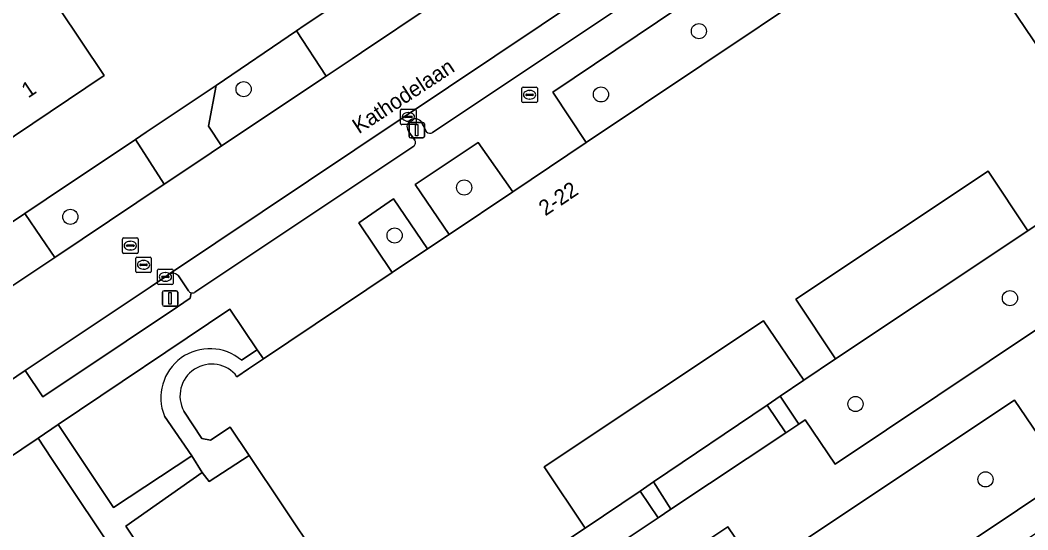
# Model space of a CAD drawing. Extents: x 158793 to 159888, y 384317 to 385256.
# Drawn here: x 158844.5 to 158909.7, y 384549.7 to 384582.6 of the extents above; entities that cross this region are included whole.
import ezdxf

# ---------------------------------------------------------------- set-up
doc = ezdxf.new("R2010")
doc.units = 0
for name, color, linetype in [('IMGEO_Berm_groen', 7, 'Continuous'), ('IMGEO_Boom', 7, 'Continuous'), ('IMGEO_Brandkraan', 7, 'Continuous'), ('IMGEO_Erf', 7, 'Continuous'), ('IMGEO_Groenvoorziening', 7, 'Continuous'), ('IMGEO_Inrit_open', 7, 'Continuous'), ('IMGEO_Kolk', 7, 'Continuous'), ('IMGEO_Lichtmast', 7, 'Continuous'), ('IMGEO_Openbare_ruimte_label', 7, 'Continuous'), ('IMGEO_Pand', 7, 'Continuous'), ('IMGEO_Pand_nummerreeks', 7, 'Continuous'), ('IMGEO_Pand_overbouw', 7, 'Continuous'), ('IMGEO_Parkeervlak_open', 7, 'Continuous'), ('IMGEO_Rijbaan_lokaal_open', 7, 'Continuous'), ('IMGEO_Rioolput', 7, 'Continuous'), ('IMGEO_Voetpad_gesloten', 7, 'Continuous'), ('IMGEO_Voetpad_halfverhard', 7, 'Continuous'), ('IMGEO_Voetpad_open', 7, 'Continuous')]:
    doc.layers.add(name, color=color, linetype=linetype)

msp = doc.modelspace()

# ---------------------------------------------------------------- linework, layer by layer
at = {"layer": 'IMGEO_Berm_groen'}
for points in [[(158854.32, 384566.248), (158854.199, 384566.219), (158854.173, 384566.208), (158854.147, 384566.195), (158854.099, 384566.166), (158853.914, 384566.031), (158852.903, 384565.347), (158844.83, 384559.95), (158845.97, 384558.247), (158851.361, 384561.842)], [(158855.384, 384565.105), (158854.738, 384566.065)], [(158851.361, 384561.842), (158854.669, 384564.066), (158855.499, 384564.624), (158855.562, 384564.977)]]:
    msp.add_lwpolyline(points, dxfattribs=at)
for centre, radius, start, end in [((158854.364, 384565.78), 0.47, 37.32016, 95.39233), ((158855.636, 384565.267), 0.299, 212.78458, 255.77551)]:
    msp.add_arc(centre, radius, start, end, dxfattribs=at)
at = {"layer": 'IMGEO_Boom'}
for centre in [(158888.4, 384581.893), (158858.951, 384578.145), (158882.064, 384577.805), (158873.216, 384571.784), (158847.744, 384569.893), (158868.717, 384568.685), (158908.517, 384564.632), (158898.529, 384557.786), (158906.935, 384552.912)]:
    msp.add_circle(centre, 0.489, dxfattribs=at)
at = {"layer": 'IMGEO_Brandkraan'}
for p, q in [((158876.948, 384577.354), (158876.948, 384578.206)), ((158877.023, 384578.28), (158877.875, 384578.28)), ((158877.949, 384578.206), (158877.949, 384577.354)), ((158877.207, 384577.774), (158877.207, 384577.786)), ((158877.645, 384577.737), (158877.247, 384577.737)), ((158877.25, 384577.823), (158877.648, 384577.823)), ((158877.436, 384578.06), (158877.461, 384578.06)), ((158877.691, 384577.786), (158877.691, 384577.774)), ((158877.875, 384577.28), (158877.023, 384577.28)), ((158877.459, 384577.5), (158877.434, 384577.5))]:
    msp.add_line(p, q, dxfattribs=at)
for points in [[(158876.948, 384577.354), (158876.948, 384578.206)], [(158877.023, 384578.28), (158877.875, 384578.28)], [(158877.949, 384578.206), (158877.949, 384577.354)], [(158877.875, 384577.28), (158877.023, 384577.28)]]:
    msp.add_lwpolyline(points, dxfattribs=at)
for centre, radius, start, end in [((158877.025, 384578.204), 0.0765, 91.55205, 178.44795), ((158877.025, 384578.204), 0.0765, 91.55205, 178.44795), ((158877.873, 384578.204), 0.0765, 1.55205, 88.44795), ((158877.873, 384578.204), 0.0765, 1.55205, 88.44795), ((158877.247, 384577.783), 0.0403, 85.87752, 175.75265), ((158877.244, 384577.773), 0.0366, 178.93798, 274.71019), ((158877.648, 384577.78), 0.043, 264.86636, 352.45326), ((158877.652, 384577.785), 0.0386, 1.73085, 96.63898), ((158877.025, 384577.356), 0.0765, 181.55205, 268.44795), ((158877.025, 384577.356), 0.0765, 181.55205, 268.44795), ((158877.873, 384577.356), 0.0765, 271.55205, 358.44795), ((158877.873, 384577.356), 0.0765, 271.55205, 358.44795)]:
    msp.add_arc(centre, radius, start, end, dxfattribs=at)
for centre, major_axis, ratio, start_param, end_param in [((158877.435, 384577.78), (-0.387, 0.002), 0.722429, 4.712389, 7.853982), ((158877.46, 384577.78), (-0.39, 0.002), 0.717154, 1.570796, 4.712389)]:
    msp.add_ellipse(centre, major_axis=major_axis, ratio=ratio, start_param=start_param, end_param=end_param, dxfattribs=at)
at = {"layer": 'IMGEO_Erf'}
msp.add_lwpolyline([(158815.511, 384607.239), (158824.8, 384593.502), (158838.699, 384572.93), (158841.845, 384568.15), (158844.791, 384570.111), (158846.183, 384571.037), (158851.961, 384574.901), (158852.64, 384575.355), (158857.172, 384578.386), (158862.362, 384581.922), (158862.863, 384582.253), (158870.987, 384587.696), (158871.33, 384587.937), (158876.65, 384591.488), (158877.708, 384592.194), (158878.556, 384592.76), (158881.626, 384594.81), (158903.507, 384608.931), (158902.593, 384610.317), (158898.058, 384617.173), (158883.161, 384639.419), (158896.259, 384659.409)], dxfattribs=at)
for points in [[(158849.483, 384585.076), (158846.99, 384583.407), (158849.927, 384579.02), (158841.803, 384573.58), (158836.037, 384582.224), (158846.653, 384589.345)], [(158909.672, 384568.992), (158907.106, 384572.842), (158894.671, 384564.558), (158897.236, 384560.707)], [(158892.814, 384557.716), (158893.655, 384558.284), (158895.186, 384559.32), (158892.571, 384563.159), (158878.397, 384553.717), (158881.04, 384549.751), (158884.602, 384552.16), (158885.469, 384552.747)]]:
    msp.add_lwpolyline(points, close=True, dxfattribs=at)
at = {"layer": 'IMGEO_Groenvoorziening'}
for points in [[(158896.066, 384584.721), (158893.869, 384587.99), (158878.954, 384577.951), (158881.101, 384574.689)], [(158864.28, 384578.99), (158862.362, 384581.922), (158857.172, 384578.386), (158856.672, 384575.759), (158857.528, 384574.48)], [(158853.808, 384571.995), (158851.961, 384574.901), (158846.183, 384571.037), (158844.791, 384570.111), (158845.852, 384568.549), (158846.731, 384567.269)], [(158874.127, 384574.707), (158870.056, 384571.973), (158872.253, 384568.757), (158876.359, 384571.51)], [(158920.463, 384569.434), (158917.313, 384574.089), (158915.672, 384572.989), (158909.672, 384568.992), (158897.236, 384560.707), (158895.186, 384559.32), (158893.655, 384558.284), (158894.867, 384556.489), (158895.279, 384556.763), (158897.216, 384553.897)], [(158868.652, 384571.046), (158866.399, 384569.501), (158868.57, 384566.288), (158870.855, 384567.82)], [(158912.188, 384553.057), (158908.819, 384558.044), (158892.215, 384546.967), (158890.278, 384549.853), (158884.582, 384546.051), (158889.87, 384538.118)], [(158894.012, 384555.92), (158892.814, 384557.716), (158885.469, 384552.747), (158886.593, 384550.985)], [(158846.53, 384554.269), (158845.658, 384555.582), (158838.061, 384550.476), (158839.557, 384548.32), (158837.723, 384547.037), (158838.14, 384546.442), (158839.403, 384544.582), (158841.647, 384546.027), (158842.852, 384544.03), (158840.786, 384542.544), (158851.128, 384527.309), (158860.392, 384533.498)], [(158859.32, 384554.45), (158856.721, 384552.773), (158856.279, 384553.362), (158851.333, 384549.895), (158861.674, 384534.354), (158872.769, 384541.766), (158871.634, 384543.486), (158868.183, 384541.187)], [(158885.76, 384550.431), (158884.602, 384552.16), (158881.04, 384549.751), (158872.46, 384544.036), (158873.576, 384542.305), (158881.227, 384547.416)]]:
    msp.add_lwpolyline(points, close=True, dxfattribs=at)
msp.add_lwpolyline([(158858.814, 384560.615), (158859.837, 384561.3), (158858.056, 384563.917), (158846.964, 384556.461), (158850.531, 384551.1), (158855.606, 384554.43), (158853.829, 384557.007)], dxfattribs=at)
msp.add_arc((158856.767, 384558.196), 3.169, 49.75731, 202.03457, dxfattribs=at)
at = {"layer": 'IMGEO_Inrit_open'}
msp.add_lwpolyline([(158871.218, 384583.628), (158873.243, 384584.982), (158871.33, 384587.937), (158870.987, 384587.696), (158862.863, 384582.253), (158862.362, 384581.922), (158864.28, 384578.99), (158865.964, 384580.114), (158866.578, 384580.525)], close=True, dxfattribs=at)
at = {"layer": 'IMGEO_Kolk'}
for p, q in [((158869.104, 384575.924), (158869.104, 384576.776)), ((158869.179, 384576.85), (158870.031, 384576.85)), ((158869.363, 384576.344), (158869.363, 384576.356)), ((158869.801, 384576.307), (158869.403, 384576.307)), ((158869.406, 384576.393), (158869.804, 384576.393)), ((158869.592, 384576.63), (158869.617, 384576.63)), ((158869.847, 384576.356), (158869.847, 384576.344)), ((158870.105, 384576.776), (158870.105, 384575.924)), ((158870.031, 384575.85), (158869.179, 384575.85)), ((158869.615, 384576.07), (158869.59, 384576.07)), ((158853.464, 384566.508), (158854.316, 384566.508)), ((158853.389, 384565.582), (158853.389, 384566.434)), ((158853.648, 384566.002), (158853.648, 384566.014)), ((158854.086, 384565.965), (158853.688, 384565.965)), ((158853.691, 384566.051), (158854.089, 384566.051)), ((158853.877, 384566.288), (158853.902, 384566.288)), ((158854.132, 384566.014), (158854.132, 384566.002)), ((158854.39, 384566.434), (158854.39, 384565.582)), ((158854.316, 384565.508), (158853.464, 384565.508)), ((158853.9, 384565.728), (158853.875, 384565.728))]:
    msp.add_line(p, q, dxfattribs=at)
for points in [[(158869.104, 384575.924), (158869.104, 384576.776)], [(158869.179, 384576.85), (158870.031, 384576.85)], [(158870.105, 384576.776), (158870.105, 384575.924)], [(158870.031, 384575.85), (158869.179, 384575.85)], [(158853.464, 384566.508), (158854.316, 384566.508)], [(158853.389, 384565.582), (158853.389, 384566.434)], [(158854.39, 384566.434), (158854.39, 384565.582)], [(158854.316, 384565.508), (158853.464, 384565.508)]]:
    msp.add_lwpolyline(points, dxfattribs=at)
for centre, radius, start, end in [((158869.181, 384576.774), 0.0765, 91.55205, 178.44795), ((158869.181, 384576.774), 0.0765, 91.55205, 178.44795), ((158869.403, 384576.353), 0.0403, 85.87752, 175.75265), ((158869.4, 384576.343), 0.0366, 178.93798, 274.71019), ((158869.804, 384576.35), 0.043, 264.86636, 352.45326), ((158869.808, 384576.355), 0.0386, 1.73085, 96.63898), ((158870.029, 384576.774), 0.0765, 1.55205, 88.44795), ((158870.029, 384576.774), 0.0765, 1.55205, 88.44795), ((158869.181, 384575.926), 0.0765, 181.55205, 268.44795), ((158869.181, 384575.926), 0.0765, 181.55205, 268.44795), ((158870.029, 384575.926), 0.0765, 271.55205, 358.44795), ((158870.029, 384575.926), 0.0765, 271.55205, 358.44795), ((158853.466, 384566.432), 0.0765, 91.55205, 178.44795), ((158853.466, 384566.432), 0.0765, 91.55205, 178.44795), ((158854.314, 384566.432), 0.0765, 1.55205, 88.44795), ((158854.314, 384566.432), 0.0765, 1.55205, 88.44795), ((158853.688, 384566.011), 0.0403, 85.87752, 175.75265), ((158853.685, 384566.001), 0.0366, 178.93798, 274.71019), ((158854.089, 384566.008), 0.043, 264.86636, 352.45326), ((158854.093, 384566.013), 0.0386, 1.73085, 96.63898), ((158853.466, 384565.584), 0.0765, 181.55205, 268.44795), ((158853.466, 384565.584), 0.0765, 181.55205, 268.44795), ((158854.314, 384565.584), 0.0765, 271.55205, 358.44795), ((158854.314, 384565.584), 0.0765, 271.55205, 358.44795)]:
    msp.add_arc(centre, radius, start, end, dxfattribs=at)
for centre, major_axis, ratio, start_param, end_param in [((158869.591, 384576.35), (-0.387, 0.002), 0.722429, 4.712389, 7.853982), ((158869.616, 384576.35), (-0.39, 0.002), 0.717154, 1.570796, 4.712389), ((158853.876, 384566.008), (-0.387, 0.002), 0.722429, 4.712389, 7.853982), ((158853.901, 384566.008), (-0.39, 0.002), 0.717154, 1.570796, 4.712389)]:
    msp.add_ellipse(centre, major_axis=major_axis, ratio=ratio, start_param=start_param, end_param=end_param, dxfattribs=at)
at = {"layer": 'IMGEO_Lichtmast'}
for p, q in [((158869.657, 384575.093), (158869.657, 384575.893)), ((158869.657, 384575.893), (158869.657, 384575.093)), ((158869.757, 384575.993), (158870.547, 384575.993)), ((158870.547, 384575.993), (158869.757, 384575.993)), ((158870.647, 384575.893), (158870.647, 384575.093)), ((158870.647, 384575.093), (158870.647, 384575.893)), ((158870.547, 384574.993), (158869.757, 384574.993)), ((158869.757, 384574.993), (158870.547, 384574.993)), ((158853.702, 384564.214), (158853.702, 384565.014)), ((158853.702, 384565.014), (158853.702, 384564.214)), ((158853.802, 384565.114), (158854.592, 384565.114)), ((158854.592, 384565.114), (158853.802, 384565.114)), ((158854.692, 384565.014), (158854.692, 384564.214)), ((158854.692, 384564.214), (158854.692, 384565.014)), ((158854.592, 384564.114), (158853.802, 384564.114)), ((158853.802, 384564.114), (158854.592, 384564.114))]:
    msp.add_line(p, q, dxfattribs=at)
for points in [[(158870.077, 384575.868), (158870.227, 384575.868), (158870.227, 384575.118), (158870.077, 384575.118), (158870.077, 384575.868)], [(158854.122, 384564.989), (158854.272, 384564.989), (158854.272, 384564.239), (158854.122, 384564.239), (158854.122, 384564.989)]]:
    msp.add_lwpolyline(points, dxfattribs=at)
for centre, start, end in [((158869.757, 384575.893), 90, 180), ((158869.757, 384575.893), 90, 180), ((158870.547, 384575.893), 0, 90), ((158870.547, 384575.893), 360, 90), ((158869.757, 384575.093), 180, 270), ((158869.757, 384575.093), 180, 270), ((158870.547, 384575.093), 270, 0), ((158870.547, 384575.093), 270, 0), ((158853.802, 384565.014), 90, 180), ((158853.802, 384565.014), 90, 180), ((158854.592, 384565.014), 0, 90), ((158854.592, 384565.014), 360, 90), ((158853.802, 384564.214), 180, 270), ((158853.802, 384564.214), 180, 270), ((158854.592, 384564.214), 270, 0), ((158854.592, 384564.214), 270, 0)]:
    msp.add_arc(centre, 0.1, start, end, dxfattribs=at)
at = {"layer": 'IMGEO_Pand'}
msp.add_lwpolyline([(158846.99, 384583.407), (158849.483, 384585.076), (158846.653, 384589.345), (158836.037, 384582.224), (158841.803, 384573.58), (158849.927, 384579.02)], close=True, dxfattribs=at)
for points in [[(158907.106, 384572.842), (158909.672, 384568.992), (158915.672, 384572.989), (158912.909, 384577.075), (158906.092, 384587.156), (158900.6, 384583.487), (158898.628, 384586.438), (158896.066, 384584.721), (158881.101, 384574.689), (158876.359, 384571.51), (158872.253, 384568.757), (158870.855, 384567.82), (158868.57, 384566.288), (158860.242, 384560.705), (158859.272, 384560.055), (158858.523, 384559.553)], [(158855.089, 384557.324), (158856.243, 384555.552), (158856.8, 384555.439), (158858.085, 384556.298), (158859.32, 384554.45), (158868.183, 384541.187), (158871.634, 384543.486), (158872.46, 384544.036), (158881.04, 384549.751), (158878.397, 384553.717), (158892.571, 384563.159), (158895.186, 384559.32), (158897.236, 384560.707), (158894.671, 384564.558), (158907.106, 384572.842)]]:
    msp.add_lwpolyline(points, dxfattribs=at)
msp.add_arc((158856.887, 384558.314), 2.052, 37.11885, 208.85613, dxfattribs=at)
at = {"layer": 'IMGEO_Pand_overbouw'}
msp.add_lwpolyline([(158918.255, 384580.636), (158911.49, 384590.763), (158906.092, 384587.156), (158912.909, 384577.075)], close=True, dxfattribs=at)
at = {"layer": 'IMGEO_Parkeervlak_open'}
for points in [[(158905.186, 384600.352), (158905.226, 384600.389), (158854.147, 384566.195), (158854.173, 384566.208), (158854.199, 384566.219), (158854.32, 384566.248)], [(158871.178, 384575.348), (158885.328, 384584.798)], [(158870.407, 384576.067), (158870.777, 384575.376)], [(158870.023, 384574.852), (158869.648, 384575.377)], [(158855.792, 384565.008), (158869.953, 384574.465)], [(158854.738, 384566.065), (158855.384, 384565.105)]]:
    msp.add_lwpolyline(points, dxfattribs=at)
for centre, radius, start, end in [((158870.03, 384575.719), 0.513, 42.68697, 221.86041), ((158870.996, 384575.633), 0.338, 229.48896, 302.5226), ((158869.796, 384574.693), 0.277, 304.59081, 34.90374), ((158854.364, 384565.78), 0.47, 37.32016, 95.39233), ((158855.636, 384565.267), 0.299, 212.78458, 255.77551), ((158855.639, 384565.275), 0.308, 255.53995, 299.81248)]:
    msp.add_arc(centre, radius, start, end, dxfattribs=at)
at = {"layer": 'IMGEO_Rijbaan_lokaal_open'}
for points in [[(158836.541, 384554.422), (158836.668, 384554.507), (158842.356, 384558.296), (158843.187, 384558.851), (158844.83, 384559.95), (158852.903, 384565.347), (158853.914, 384566.031), (158854.099, 384566.166), (158854.147, 384566.195), (158905.226, 384600.389)], [(158871.218, 384583.628), (158866.578, 384580.525), (158865.964, 384580.114), (158864.28, 384578.99), (158857.528, 384574.48), (158856.19, 384573.586), (158853.808, 384571.995), (158846.731, 384567.269), (158843.757, 384565.282), (158838.751, 384561.939), (158837.652, 384561.205), (158837.35, 384561.007), (158834.833, 384559.355), (158834.3, 384559.005), (158833.447, 384558.487)]]:
    msp.add_lwpolyline(points, dxfattribs=at)
for points in [[(158856.672, 384575.759), (158857.172, 384578.386), (158852.64, 384575.355), (158851.961, 384574.901), (158853.808, 384571.995), (158856.19, 384573.586), (158857.528, 384574.48)], [(158845.852, 384568.549), (158844.791, 384570.111), (158841.845, 384568.15), (158841.863, 384568.123), (158843.757, 384565.282), (158846.731, 384567.269)]]:
    msp.add_lwpolyline(points, close=True, dxfattribs=at)
at = {"layer": 'IMGEO_Rioolput'}
for p, q in [((158851.121, 384567.6), (158851.121, 384568.452)), ((158851.196, 384568.526), (158852.048, 384568.526)), ((158852.122, 384568.452), (158852.122, 384567.6)), ((158851.38, 384568.02), (158851.38, 384568.032)), ((158851.818, 384567.983), (158851.42, 384567.983)), ((158851.423, 384568.069), (158851.821, 384568.069)), ((158851.632, 384567.746), (158851.607, 384567.746)), ((158851.609, 384568.306), (158851.634, 384568.306)), ((158851.864, 384568.032), (158851.864, 384568.02)), ((158852.048, 384567.526), (158851.196, 384567.526)), ((158851.979, 384566.361), (158851.979, 384567.213)), ((158852.054, 384567.287), (158852.906, 384567.287)), ((158852.98, 384567.213), (158852.98, 384566.361)), ((158852.238, 384566.781), (158852.238, 384566.793)), ((158852.676, 384566.744), (158852.278, 384566.744)), ((158852.281, 384566.83), (158852.679, 384566.83)), ((158852.49, 384566.507), (158852.465, 384566.507)), ((158852.467, 384567.067), (158852.492, 384567.067)), ((158852.722, 384566.793), (158852.722, 384566.781)), ((158852.906, 384566.287), (158852.054, 384566.287))]:
    msp.add_line(p, q, dxfattribs=at)
for points in [[(158851.121, 384567.6), (158851.121, 384568.452)], [(158851.196, 384568.526), (158852.048, 384568.526)], [(158852.122, 384568.452), (158852.122, 384567.6)], [(158852.048, 384567.526), (158851.196, 384567.526)], [(158851.979, 384566.361), (158851.979, 384567.213)], [(158852.054, 384567.287), (158852.906, 384567.287)], [(158852.98, 384567.213), (158852.98, 384566.361)], [(158852.906, 384566.287), (158852.054, 384566.287)]]:
    msp.add_lwpolyline(points, dxfattribs=at)
for centre, radius, start, end in [((158851.198, 384568.45), 0.0765, 91.55205, 178.44795), ((158851.198, 384568.45), 0.0765, 91.55205, 178.44795), ((158852.046, 384568.45), 0.0765, 1.55205, 88.44795), ((158852.046, 384568.45), 0.0765, 1.55205, 88.44795), ((158851.42, 384568.029), 0.0403, 85.87752, 175.75265), ((158851.417, 384568.019), 0.0366, 178.93798, 274.71019), ((158851.821, 384568.026), 0.043, 264.86636, 352.45326), ((158851.825, 384568.031), 0.0386, 1.73085, 96.63898), ((158851.198, 384567.602), 0.0765, 181.55205, 268.44795), ((158851.198, 384567.602), 0.0765, 181.55205, 268.44795), ((158852.056, 384567.211), 0.0765, 91.55205, 178.44795), ((158852.056, 384567.211), 0.0765, 91.55205, 178.44795), ((158852.046, 384567.602), 0.0765, 271.55205, 358.44795), ((158852.046, 384567.602), 0.0765, 271.55205, 358.44795), ((158852.904, 384567.211), 0.0765, 1.55205, 88.44795), ((158852.904, 384567.211), 0.0765, 1.55205, 88.44795), ((158852.278, 384566.79), 0.0403, 85.87752, 175.75265), ((158852.275, 384566.78), 0.0366, 178.93798, 274.71019), ((158852.679, 384566.787), 0.043, 264.86636, 352.45326), ((158852.683, 384566.792), 0.0386, 1.73085, 96.63898), ((158852.056, 384566.363), 0.0765, 181.55205, 268.44795), ((158852.056, 384566.363), 0.0765, 181.55205, 268.44795), ((158852.904, 384566.363), 0.0765, 271.55205, 358.44795), ((158852.904, 384566.363), 0.0765, 271.55205, 358.44795)]:
    msp.add_arc(centre, radius, start, end, dxfattribs=at)
for centre, major_axis, ratio, start_param, end_param in [((158851.608, 384568.026), (-0.387, 0.002), 0.722429, 4.712389, 7.853982), ((158851.633, 384568.026), (-0.39, 0.002), 0.717154, 1.570796, 4.712389), ((158852.466, 384566.787), (-0.387, 0.002), 0.722429, 4.712389, 7.853982), ((158852.491, 384566.787), (-0.39, 0.002), 0.717154, 1.570796, 4.712389)]:
    msp.add_ellipse(centre, major_axis=major_axis, ratio=ratio, start_param=start_param, end_param=end_param, dxfattribs=at)
at = {"layer": 'IMGEO_Voetpad_gesloten'}
msp.add_lwpolyline([(158920.463, 384569.434), (158897.216, 384553.897), (158895.279, 384556.763), (158894.867, 384556.489), (158894.012, 384555.92), (158886.593, 384550.985), (158885.76, 384550.431), (158881.227, 384547.416), (158873.576, 384542.305), (158872.769, 384541.766), (158861.674, 384534.354), (158860.392, 384533.498), (158851.128, 384527.309), (158852.808, 384524.835), (158862.048, 384531.017), (158863.336, 384531.857), (158882.889, 384544.918), (158888.254, 384537.037), (158889.87, 384538.118), (158884.582, 384546.051), (158890.278, 384549.853), (158892.215, 384546.967), (158908.819, 384558.044), (158912.188, 384553.057)], dxfattribs=at)
msp.add_lwpolyline([(158856.279, 384553.362), (158855.606, 384554.43), (158850.531, 384551.1), (158846.964, 384556.461), (158845.658, 384555.582), (158846.53, 384554.269), (158860.392, 384533.498), (158861.674, 384534.354), (158851.333, 384549.895)], close=True, dxfattribs=at)
at = {"layer": 'IMGEO_Voetpad_halfverhard'}
for points in [[(158893.655, 384558.284), (158892.814, 384557.716), (158894.012, 384555.92), (158894.867, 384556.489)], [(158885.469, 384552.747), (158884.602, 384552.16), (158885.76, 384550.431), (158886.593, 384550.985)]]:
    msp.add_lwpolyline(points, close=True, dxfattribs=at)
at = {"layer": 'IMGEO_Voetpad_open'}
for points in [[(158874.127, 384574.707), (158876.359, 384571.51), (158881.101, 384574.689), (158878.954, 384577.951), (158893.869, 384587.99), (158898.293, 384590.919), (158907.433, 384597), (158906.179, 384598.54), (158905.751, 384598.386), (158886.591, 384585.621)], [(158906.092, 384587.156), (158912.909, 384577.075), (158915.672, 384572.989), (158917.313, 384574.089), (158918.982, 384575.206), (158920.985, 384576.549), (158918.255, 384580.636), (158911.49, 384590.763)], [(158885.328, 384584.798), (158871.178, 384575.348)], [(158870.777, 384575.376), (158870.407, 384576.067)], [(158869.648, 384575.377), (158870.023, 384574.852)], [(158838.061, 384550.476), (158845.658, 384555.582), (158846.964, 384556.461), (158858.056, 384563.917), (158859.837, 384561.3), (158860.242, 384560.705), (158868.57, 384566.288), (158866.399, 384569.501), (158868.652, 384571.046), (158870.855, 384567.82), (158872.253, 384568.757), (158870.056, 384571.973), (158874.127, 384574.707)], [(158869.953, 384574.465), (158855.792, 384565.008)], [(158855.562, 384564.977), (158855.499, 384564.624), (158854.669, 384564.066), (158851.361, 384561.842), (158845.97, 384558.247), (158844.83, 384559.95), (158843.187, 384558.851)], [(158858.523, 384559.553), (158859.272, 384560.055), (158860.242, 384560.705), (158859.837, 384561.3), (158858.814, 384560.615)], [(158858.085, 384556.298), (158856.8, 384555.439), (158856.243, 384555.552), (158855.089, 384557.324)], [(158853.829, 384557.007), (158855.606, 384554.43), (158856.279, 384553.362), (158856.721, 384552.773), (158859.32, 384554.45), (158858.085, 384556.298)]]:
    msp.add_lwpolyline(points, dxfattribs=at)
msp.add_lwpolyline([(158916.291, 384553.522), (158920.835, 384556.571), (158925.371, 384559.632), (158929.912, 384562.685), (158934.472, 384565.722), (158934.973, 384566.056), (158933.922, 384567.605), (158913.823, 384554.152), (158912.188, 384553.057), (158889.87, 384538.118), (158888.254, 384537.037), (158889.013, 384535.927), (158889.357, 384535.423), (158893.873, 384538.46), (158898.464, 384541.547), (158903.083, 384544.653), (158907.238, 384547.447), (158911.747, 384550.473)], close=True, dxfattribs=at)
for centre, radius, start, end in [((158870.03, 384575.719), 0.513, 42.68697, 221.86041), ((158870.996, 384575.633), 0.338, 229.48896, 302.5226), ((158869.796, 384574.693), 0.277, 304.59081, 34.90374), ((158855.639, 384565.275), 0.308, 255.53995, 299.81248), ((158856.767, 384558.196), 3.169, 49.75731, 202.03457), ((158856.887, 384558.314), 2.052, 37.11885, 208.85613)]:
    msp.add_arc(centre, radius, start, end, dxfattribs=at)

# ---------------------------------------------------------------- texts
at = {"layer": 'IMGEO_Openbare_ruimte_label'}
msp.add_text('Kathodelaan', height=1, rotation=33.24494, dxfattribs=at).set_placement((158866.406, 384575.225))
at = {"layer": 'IMGEO_Pand_nummerreeks'}
for s, rotation, p in [('1', 33.80447, (158845.014, 384577.535)), ('2-22', 33.83889, (158878.467, 384569.913))]:
    msp.add_text(s, height=1, rotation=rotation, dxfattribs=at).set_placement(p)

doc.saveas('drawing.dxf')
